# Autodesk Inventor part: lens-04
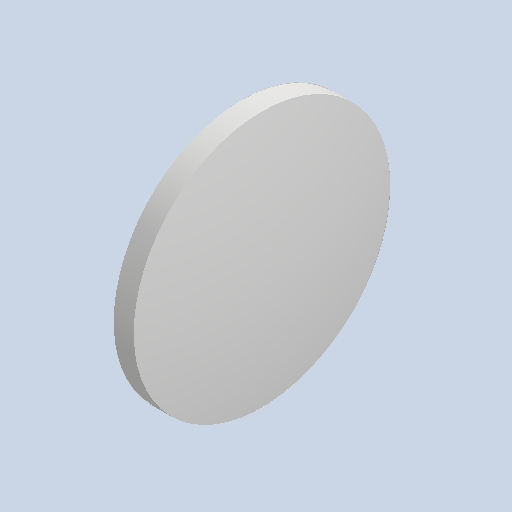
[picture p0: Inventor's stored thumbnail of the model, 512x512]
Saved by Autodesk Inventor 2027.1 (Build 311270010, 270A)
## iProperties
Created: 2026-07
Part Number: lens-04
Material: Generic
Document SubType Name: Modeling
Designer: dunge
Density: 1 g/cm^3
Appearance: Default
Author: dunge
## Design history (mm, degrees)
derived "lens.ipt"
feature "Lens::lens.ipt"
tag "TaggingFeature1"
node "Finishes"
node "Lens"
node "Finish1" dims "Finish1_Area" = 302.50437
other parameters: "SIDE_2_MINOR" = 0.635, "LENS_RADIUS" = 20.32, "SIDE_1_MINOR" = 2.54, "SIDE_1_MAJOR" = 5.08, "SIDE_2_MAJOR" = 1.905
